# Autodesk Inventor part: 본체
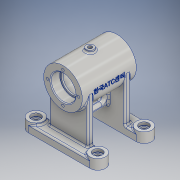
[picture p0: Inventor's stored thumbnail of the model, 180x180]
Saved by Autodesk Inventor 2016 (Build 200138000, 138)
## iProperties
Created: 2015-11
Part Number: 본체
Material: 알루미늄 6061
Document SubType Name: Modeling
Designer: Administrator
Density: 2.7 g/cm^3
Appearance: 알루미늄 - 평지
Mass: 355.433 g
Surface Area: 458.771 cm^2
Volume: 131.642 cm^3
Author: Administrator
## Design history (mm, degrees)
sketch "스케치2"
  geometry: L1 (-40, 40)-(40, 40); L2 (40, 20)-(-40, 20); L3 (63.121, 0)-(-63.121, 0); L4 (-40, -40)-(40, -40); L5 (40, -20)-(-40, -20); A1 r 10 centre (-40, 30) between (-40, 40) and (-40, 20); A2 r 10 centre (40, 30) between (40, 20) and (40, 40); A3 r 10 centre (-40, -30) between (-40, -20) and (-40, -40); A4 r 10 centre (40, -30) between (40, -40) and (40, -20); 4 further points
  constraints: 10 end point, 8 point on circle, 7 symmetric about line, 4 centre point, 2 horizontal, 2 midpoint, 1 coincident, 1 horizontal alignment, 1 parallel, 1 tangent, 2 other
  dimensions: "d18" = 80 distance of A2.centre A1.centre; "d19" = 40 horizontal distance of point (0, 0) A1.centre; "d22" = 40 distance from line of point (0, 0) L1; "d23" = 20 distance between parallel lines of L2 L1; "d24" = 10 radius of A2; "d25" = 10 radius of A1
extrude "돌출1" new body sketch "스케치2" distance "d26" = 10; taper "d27" = 0 deg
sketch "스케치3"
  geometry: L1 (40, 40)-(-40, 40) reference; L2 (-40, 20)-(40, 20) reference; L3 (-78.132, 0)-(78.132, 0); L4 (-25, 20)-(-25, 28); L5 (-25, 28)-(25, 28); L6 (25, 28)-(25, 20); L7 (-40, 20)-(40, 20) reference; L8 (-25, 20)-(25, 20); L9 (-25, -20)-(-25, -28); L10 (-25, -28)-(25, -28); L11 (25, -28)-(25, -20); L12 (-25, -20)-(25, -20); L13 (40, -20)-(-40, -20) reference; A1 r 10 centre (-40, 30) between (-40, 40) and (-40, 20) reference; A2 r 10 centre (40, 30) between (40, 20) and (40, 40) reference; 4 further points
  constraints: 18 end point, 5 symmetric about line, 2 collinear, 2 midpoint, 2 perpendicular, 2 point on line, 1 coincident, 1 horizontal, 1 vertical, 1 vertical alignment
  dimensions: "d28" = 8 distance between parallel lines of L2 L5; "d29" = 50 distance between parallel lines of L4 L6
extrude "돌출2" join sketch "스케치3" distance "d30" = 58; taper "d31" = 0 deg
sketch "스케치4"
  geometry: L1 (-25, 20)-(-25, 28) reference; L2 (-25, 28)-(25, 28) reference; L3 (25, 28)-(25, 20) reference; L4 (25, 20)-(40, 20) reference; L5 (40, 40)-(-40, 40) reference; L6 (-40, 20)-(-25, 20) reference; C1 r 10 at (-40, 30); C2 r 10 at (40, 30); A1 r 10 centre (40, 30) between (40, 20) and (40, 40) reference; A2 r 10 centre (-40, 30) between (-40, 40) and (-40, 20) reference; 1 further point
  constraints: 2 centre point, 2 coincident
  dimensions: "d32" = 20 diameter of C1; "d33" = 20 diameter of C2
extrude "돌출3" join sketch "스케치4" distance "d34" = 3; taper "d35" = 0 deg
sketch "스케치8"
  geometry: C1 r 25 at (0, 68); 1 further point
  constraints: 1 centre point, 1 vertical alignment
  dimensions: "d48" = 50 diameter of C1; "d49" = 68 distance of point (0, 0) C1.centre
extrude "돌출6" join sketch "스케치8" stored distance "d50" = 70; taper "d51" = 0 deg
node "작업 평면2"
sketch "스케치9"
  geometry: C1 r 5 at (0, 0); 1 further point
  constraints: 1 centre point, 1 coincident
  dimensions: "d52" = 10 diameter of C1
extrude "돌출7" join sketch "스케치9" distance "d53" = 3; taper "d55" = 0 deg; dims "d54" = 14.5, "d56" = 0
sketch "스케치10"
  geometry: L1 (0, 68)-(0, 29.545); L2 (0, 68)-(15.822, 40.595); A1 r 25 centre (0, 68) between (-25, 68) and (25, 68) reference; 3 further points
  constraints: 4 end point, 1 midpoint, 1 point on circle, 1 point on line, 1 vertical, 1 vertical alignment
  dimensions: "d57" = 68 distance of point (0, 0) L1.start; "d58" = 30 deg angle of L1 L2
node "작업 평면3"
sketch "스케치13"
  geometry: L1 (10, 28)-(68, 28) reference; L2 (68, 20)-(68, 28) reference; L3 (10, 20)-(68, 20) reference; L4 (10, 28)-(10, 20) reference; L5 (10, -20)-(68, -20) reference; L6 (68, -28)-(68, -20) reference; L7 (10, -28)-(68, -28) reference; L8 (10, -20)-(10, -28) reference; L9 (45, 20)-(23, 20); L10 (23, 20)-(23, -20); L11 (23, -20)-(45, -20); L12 (45, -20)-(45, 20); L13 (33, 31.422)-(33, -31.422); L14 (0, 40)-(0, 20) reference; 4 further points
  constraints: 10 end point, 3 midpoint, 2 horizontal alignment, 2 parallel, 1 horizontal, 1 perpendicular, 1 vertical
  dimensions: "d70" = 22 distance of L10.end L11.end; "d71" = 40 distance of L9.end L10.end; "d72" = 12 distance between parallel lines of L13 L12; "d74" = 33 distance from line of L14 point (33, 0)
extrude "돌출9" join sketch "스케치13" stored distance "d75" = 8; taper "d76" = 0 deg
sketch "스케치14"
  geometry: L1 (-20, 23)-(-20, 43.322) reference; L2 (-20, 23)-(20, 23) reference; L3 (20, 43.322)-(20, 23) reference; L4 (-11.5, 36.5)-(11.5, 36.5); L5 (11.5, 29.5)-(-11.5, 29.5); L6 (-15.947, 33)-(15.947, 33); L7 (-20, 43.322)-(20, 43.322) reference; A1 r 3.5 centre (-11.5, 33) between (-11.5, 36.5) and (-11.5, 29.5); A2 r 3.5 centre (11.5, 33) between (11.5, 29.5) and (11.5, 36.5); 3 further points
  constraints: 6 end point, 4 point on circle, 2 centre point, 2 horizontal, 2 midpoint, 2 vertical alignment, 1 parallel, 1 point on line, 1 tangent
  dimensions: "d79" = 33 distance of point (0, 0) point (0, 33); "d82" = 23 distance of A2.centre A1.centre; "d83" = 3.5 radius of A2; "d84" = 7 distance between parallel lines of L5 L4; "d85" = 3.5 radius of A1; "d176" = 11.5 distance of A1.centre point (0, 33)
extrude "돌출10" cut sketch "스케치14" stored distance "d86" = 8; taper "d87" = 0 deg
fillet "모깎기1" dims "d88" = 3.5
sketch "스케치15"
  geometry: C1 r 10 at (0, 0) reference; C2 r 6 at (0, 0); 1 further point
  constraints: 1 centre point, 1 coincident
  dimensions: "d89" = 12 diameter of C2
extrude "돌출11" cut sketch "스케치15" distance "d90" = 4; taper "d91" = 0 deg
sketch "스케치16"
  geometry: C1 r 6 at (0, 0) reference; C2 r 3 at (0, 0); 1 further point
  constraints: 1 centre point, 1 coincident
  dimensions: "d92" = 6 diameter of C2
extrude "돌출12" cut sketch "스케치16" stored distance "d93" = 4; taper "d94" = 0 deg
fillet "모깎기2" dims "d95" = 0.3
chamfer "모따기1" distance "d96" = 1; stored, may be unused: second distance "d97" = 2, angle "d98" = 45 deg
sketch "스케치17"
  geometry: C1 r 10 at (-80, 60) reference; C2 r 10 at (0, 0) reference; C3 r 10 at (0, 60) reference; C4 r 6 at (-80, 60); C5 r 6 at (0, 60); C6 r 6 at (0, 0); 1 further point
  constraints: 3 centre point, 3 coincident
  dimensions: "d99" = 12 diameter of C4; "d100" = 12 diameter of C5; "d101" = 12 diameter of C6
extrude "돌출13" cut sketch "스케치17" distance "d102" = 4; taper "d103" = 0 deg
sketch "스케치18"
  geometry: C1 r 6 at (0, 0) reference; C2 r 6 at (80, 0) reference; C3 r 6 at (80, -60) reference; C4 r 3 at (0, 0); C5 r 3 at (80, 0); C6 r 3 at (80, -60); 1 further point
  constraints: 3 centre point, 3 coincident
  dimensions: "d104" = 6 diameter of C4; "d105" = 6 diameter of C5; "d106" = 6 diameter of C6
extrude "돌출14" cut sketch "스케치18" stored distance "d107" = 4; taper "d108" = 0 deg
fillet "모깎기3" dims "d109" = 0.3
chamfer "모따기2" distance "d110" = 1; stored, may be unused: second distance "d111" = 2, angle "d112" = 45 deg
sketch "스케치19"
  geometry: L1 (93, 35)-(43, 35) reference; L2 (68, 43.747)-(68, -47.981); L3 (84, 35)-(84, 23.3); L4 (83.7, 23)-(82, 23); L5 (82, 23)-(82, 21); L6 (82, 21)-(86, 21); L7 (89, 18)-(89, -18); L8 (86, -21)-(82, -21); L9 (82, -21)-(82, -23); L10 (82, -23)-(83.7, -23); L11 (84, -23.3)-(84, -35); L12 (43, -35)-(93, -35) reference; L13 (84, -35)-(68, -35); L14 (84, 35)-(68, 35); L15 (68, 35)-(68, -35); A1 r 3 centre (86, 18) between (89, 18) and (86, 21); A2 r 3 centre (86, -18) between (86, -21) and (89, -18); A3 r 0.3 centre (83.7, 23.3) between (83.7, 23) and (84, 23.3); A4 r 0.3 centre (83.7, -23.3) between (84, -23.3) and (83.7, -23); 3 further points
  constraints: 26 end point, 11 point on line, 8 point on circle, 8 tangent, 6 perpendicular, 4 centre point, 2 collinear, 2 equal radius, 2 midpoint, 2 vertical
  dimensions: "d113" = 12 distance of L3.start point (84, 23); "d114" = 42 distance between parallel lines of L8 L6; "d115" = 12 distance of point (84, -23) L11.end; "d116" = 32 diameter of L3 L2; "d117" = 28 diameter of L5 L2; "d118" = 42 diameter of L7 L2; "d119" = 3 radius of A1; "d120" = 0.3 radius of A3
revolve "회전1" sketch "스케치19" stored, may be unused: angle "d121" = 90 deg
chamfer "모따기3" distance "d122" = 1; stored, may be unused: second distance "d123" = 2, angle "d124" = 45 deg
sketch "스케치20" dims "d125" = 40
  geometry: C1 r 21 at (0, 0) reference; 6 further points
  constraints: 2 vertical alignment, 1 coincident, 7 other
  dimensions: "d128" = 360 deg dimension on C1.centre point (0, 20) (derived)
hole "구멍1" sketch "스케치20" at (0, 20), (-20, 0), (0, -20), (20, 0) diameter "d130" = 3.242; stored, may be unused: countersink angle "d134" = 90 deg, drill point angle "d136" = 118 deg; dims "d131" = 8, "d132" = 4, "d133" = 2, "d135" = 10
sketch "스케치21"
  geometry: 2 further points
  constraints: 1 coincident
hole "구멍2" sketch "스케치21" at (0, 0) diameter "d137" = 5.188; stored, may be unused: countersink angle "d141" = 90 deg, drill point angle "d143" = 118 deg; dims "d138" = 12, "d139" = 4, "d140" = 2, "d142" = 25.75
fillet "모깎기4" dims "d151" = 2
fillet "모깎기5" dims "d152" = 2
fillet "모깎기6" dims "d153" = 2
node "작업 평면5"
node "작업 평면6"
sketch "스케치25"
  geometry: L1 (25, -35)-(25, 35) reference; 2 further points
  constraints: 1 horizontal alignment, 1 other
  dimensions: "d157" = 25 distance from line of point (0, 0) L1
feature "엠보싱2" sketch "스케치25" dims "d158" = 0.5, "d159" = 0
sketch "스케치26"
  geometry: L1 (0, 68)-(0, -18.265); L2 (0, 68)-(-25.435, 23.946); C1 r 14 at (0, 68) reference; A1 r 25 centre (0, 68) between (-21.296, 54.905) and (-5.556, 43.625) reference; 2 further points
  constraints: 4 end point, 1 point on circle, 1 point on line, 1 vertical
  dimensions: "d160" = 30 deg angle of L1 L2
node "작업 평면7"
sketch "스케치27"
  geometry: L1 (-25, -35)-(-25, 35) reference; C1 r 5 at (0, 0); 1 further point
  constraints: 1 centre point, 1 horizontal alignment
  dimensions: "d161" = 10 diameter of C1; "d162" = 25 distance from line of C1.centre L1
extrude "돌출15" join sketch "스케치27" distance "d163" = 3; taper "d165" = 0 deg; dims "d164" = 1.5, "d166" = 0
fillet "모깎기7" dims "d167" = 2
sketch "스케치28"
  geometry: C1 r 5 at (0, 0) reference; 2 further points
  constraints: 1 coincident
hole "구멍4" sketch "스케치28" at (0, 0) diameter "d168" = 5.188; stored, may be unused: countersink angle "d172" = 90 deg, drill point angle "d174" = 118 deg; dims "d169" = 12, "d170" = 4, "d171" = 2, "d173" = 16
fillet "모깎기8" dims "d177" = 2
node "솔리드1"
mirror "대칭1"
mirror "대칭2"
node "투영된 루프1"
node "투영된 루프2"
node "투영된 루프4"
node "투영된 루프5"
node "투영된 루프6"
node "투영된 루프7"
node "투영된 루프8"
node "투영된 루프9"
node "투영된 루프10"
node "투영된 루프11"
node "투영된 루프12"
node "투영된 루프13"
node "투영된 루프14"
node "투영된 루프16"
